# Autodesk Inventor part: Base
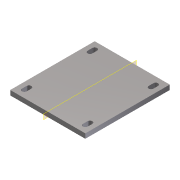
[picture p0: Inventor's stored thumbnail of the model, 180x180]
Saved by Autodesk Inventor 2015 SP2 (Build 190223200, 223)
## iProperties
Created: 2020-01
Part Number: Base
Material: 一般
Document SubType Name: Modeling
Designer: Kuan_Lun Hsu
Density: 1 g/cm^3
Appearance: 預設
Author: Kuan_Lun Hsu
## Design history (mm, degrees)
node "Weld Bracket.sat1"
node "工作平面1"
node "實體1"
node "Base1"
